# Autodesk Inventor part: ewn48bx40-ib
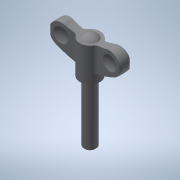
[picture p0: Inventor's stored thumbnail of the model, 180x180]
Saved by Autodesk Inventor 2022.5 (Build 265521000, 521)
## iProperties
Created: 2017-05
Part Number: ewn48bx40-ib
Material: 一般
Document SubType Name: Modeling
Designer: imaocorp
Density: 1 g/cm^3
Appearance: 既定
Author: imaocorp
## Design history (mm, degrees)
node "ewn48bx40-ib.x_t1"
node "ewn48bx40-ib"
node "Base1"
